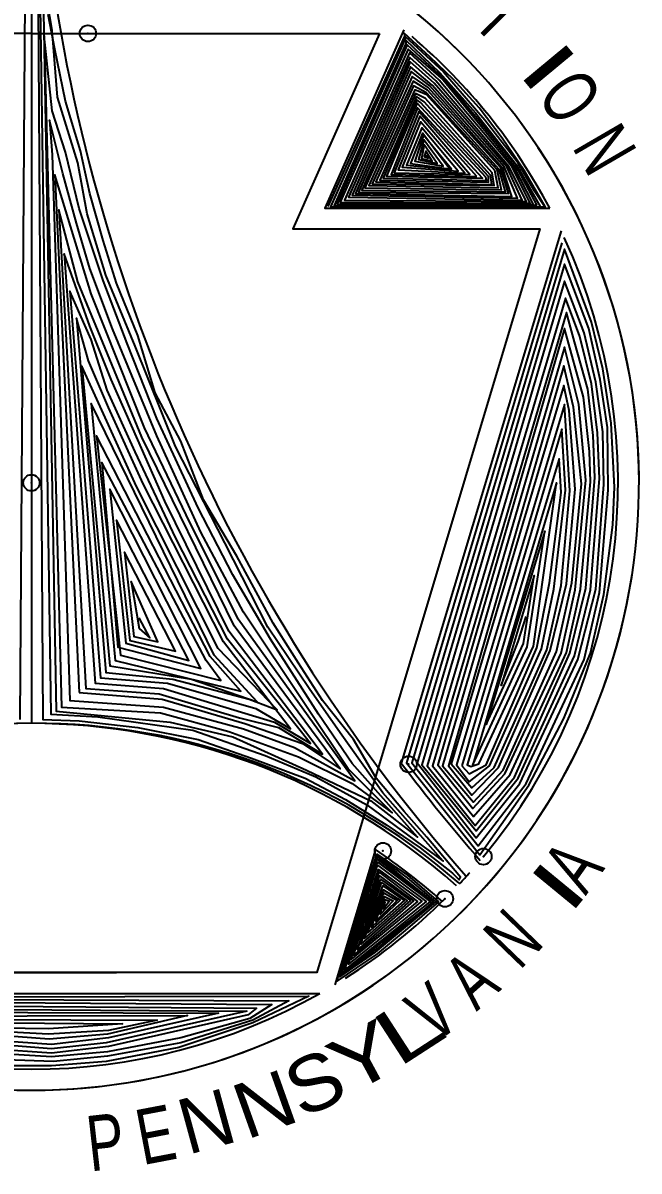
# Model space of a CAD drawing. Extents: x 763.8 to 797.8, y -170.3 to -127.3.
# Drawn here: x 780.741 to 782.194, y -131.5 to -128.791 of the extents above; entities that cross this region are included whole.
import ezdxf
from ezdxf.enums import TextEntityAlignment as Align

# ---------------------------------------------------------------- set-up
doc = ezdxf.new("R2010")
doc.units = 0
doc.header["$LTSCALE"] = 0.077
doc.header["$PDMODE"] = 32
doc.header["$PDSIZE"] = 0.0385
doc.layers.add('1', color=7, linetype='Continuous', lineweight=35)
doc.layers.add('2', color=7, linetype='Continuous')

msp = doc.modelspace()

# ---------------------------------------------------------------- linework, layer by layer
at = {"layer": '1'}
for p, q in [((780.76075, -128.49192), (780.76075, -130.44333)), ((780.75875, -128.81508), (779.93925, -128.81508)), ((780.76275, -128.81508), (781.58217, -128.81508)), ((782.01025, -129.28092), (781.63325, -130.53733)), ((781.57208, -130.74142), (781.47642, -131.06025)), ((780.08033, -131.08092), (781.44117, -131.08092))]:
    msp.add_line(p, q, dxfattribs=at)
for points in [[(780.74633, -128.50825), (780.73367, -130.434)], [(780.77517, -128.50825), (780.78775, -130.434), (780.873, -130.43717), (781.01192, -130.45292), (781.154, -130.48142), (781.28025, -130.52558), (781.40658, -130.57292), (781.50125, -130.62342), (781.59917, -130.68342), (781.67808, -130.73708), (781.75383, -130.79708), (781.76958, -130.81283), (781.77275, -130.80658), (781.69383, -130.71183), (781.64017, -130.65183), (781.57392, -130.57292), (781.52025, -130.48142), (781.44758, -130.38983), (781.39075, -130.30142), (781.33075, -130.20667), (781.24558, -130.04883), (781.16658, -129.91625), (781.11292, -129.77733), (781.053, -129.66367), (781.01192, -129.52792), (780.96142, -129.40483), (780.92983, -129.30383), (780.89825, -129.19333), (780.87617, -129.09225), (780.84142, -128.97542), (780.81617, -128.85233), (780.80042, -128.77025)], [(780.7815, -128.75133), (780.80675, -130.42142), (780.91725, -130.42775), (781.14133, -130.45925), (781.31183, -130.51925), (781.43183, -130.56975), (781.55175, -130.63608), (781.73175, -130.76867), (781.58967, -130.60767), (781.48867, -130.46558), (781.416, -130.36142), (781.31817, -130.21617), (781.21717, -130.01733), (781.10033, -129.79), (781.00558, -129.55317), (780.93617, -129.38592), (780.89192, -129.24067), (780.86983, -129.12067), (780.8225, -128.966), (780.80983, -128.80808), (780.78775, -128.67867), (780.81933, -130.41508), (781.08775, -130.44033), (781.23608, -130.47508), (781.40975, -130.554), (781.56125, -130.62658), (781.67175, -130.71183), (781.51708, -130.53817), (781.43817, -130.42142), (781.3245, -130.24458), (781.23608, -130.09308), (781.154, -129.93517), (781.05617, -129.72367), (780.98667, -129.54692), (780.92983, -129.3985), (780.873, -129.228), (780.84142, -129.09542), (780.80983, -128.99758), (780.79092, -128.82075), (780.832, -130.40558), (781.06558, -130.41825), (781.22658, -130.46242), (781.39075, -130.52242), (781.51708, -130.58558), (781.61175, -130.655), (781.50758, -130.55083), (781.40658, -130.39933), (781.26133, -130.18142), (781.16033, -129.992), (781.05617, -129.76475), (780.95192, -129.51217), (780.89825, -129.37008), (780.86667, -129.26275), (780.83517, -129.14592), (780.80358, -129.01967), (780.80983, -129.10175), (780.85092, -130.38983), (781.07192, -130.40558), (781.26133, -130.45608), (781.38125, -130.50033), (781.52333, -130.57925), (781.24875, -130.19725), (781.12558, -129.951), (781.02775, -129.74575), (780.90142, -129.43008), (780.81617, -129.14908), (780.873, -130.37083)], [(781.63958, -128.80683), (781.45258, -129.22758), (781.98342, -129.22758)], [(779.93925, -128.81508), (780.1445, -129.27675), (779.56125, -129.27675), (780.08775, -131.03175), (780.96133, -131.03175)], [(781.58217, -128.81508), (781.377, -129.27675), (781.96017, -129.27675), (781.43367, -131.03175), (780.56017, -131.03175)], [(781.46058, -129.22358), (781.64142, -128.82158), (781.73275, -128.90617), (781.83008, -129.01917), (781.90675, -129.11742), (781.94508, -129.18325), (781.97258, -129.2255), (781.46742, -129.22458), (781.64242, -128.8295), (781.72392, -128.90808), (781.80842, -129.00242), (781.90475, -129.12533), (781.96075, -129.22358), (781.97258, -129.22458), (781.92342, -129.13908), (781.87133, -129.06242), (781.81725, -128.99067), (781.75633, -128.92383), (781.70033, -128.87075), (781.64042, -128.81475), (781.64433, -128.83933), (781.47525, -129.22158), (781.95292, -129.21967), (781.90375, -129.12725), (781.8055, -129.00733), (781.73175, -128.92092), (781.64733, -128.84225), (781.48217, -129.21767), (781.94508, -129.21867), (781.89883, -129.12825), (781.72783, -128.92092), (781.64925, -128.85208), (781.48908, -129.21375), (781.93725, -129.21575), (781.89392, -129.12925), (781.72292, -128.92583), (781.65225, -128.86092), (781.49892, -129.20883), (781.92833, -129.21175), (781.88708, -129.12925), (781.71508, -128.92675), (781.65317, -128.87175), (781.50875, -129.20192), (781.9185, -129.20883), (781.88217, -129.13025), (781.71117, -128.93267), (781.65417, -128.8825), (781.51758, -129.197), (781.90775, -129.20392), (781.87625, -129.13025), (781.70625, -128.93758), (781.65517, -128.89433), (781.52542, -129.19308), (781.89392, -129.2), (781.87233, -129.13217), (781.70033, -128.93858), (781.65617, -128.90517), (781.53233, -129.19017), (781.88608, -129.19308), (781.86842, -129.13217), (781.69642, -128.9425), (781.65908, -128.91692), (781.54017, -129.18525), (781.87925, -129.18917), (781.8645, -129.13608), (781.69542, -128.94942), (781.66108, -128.92775), (781.54708, -129.17933), (781.86942, -129.18425), (781.85958, -129.13708), (781.6925, -128.95525), (781.66208, -128.93858), (781.55683, -129.17442), (781.8615, -129.17933), (781.85367, -129.13908), (781.6935, -128.96017), (781.665, -128.94842), (781.56475, -129.1705), (781.85267, -129.17442), (781.84775, -129.144), (781.6905, -128.969), (781.66692, -128.95725), (781.57358, -129.16558), (781.84675, -129.1715), (781.84383, -129.14992), (781.68758, -128.97692), (781.66892, -128.96408), (781.58242, -129.16167), (781.83892, -129.16658), (781.83892, -129.15283), (781.67875, -128.97783), (781.66992, -128.972), (781.59025, -129.15675), (781.834, -129.16267), (781.833, -129.15475), (781.67092, -128.97983), (781.59817, -129.15183), (781.82517, -129.15675), (781.67183, -128.99067), (781.609, -129.14792), (781.81142, -129.15283)], [(781.81142, -129.15283), (781.67483, -128.9995), (781.61683, -129.144), (781.79475, -129.14792), (781.67675, -129.01033), (781.62567, -129.13708), (781.78292, -129.14492), (781.67875, -129.02408), (781.6355, -129.13117), (781.76717, -129.14), (781.68175, -129.03783), (781.64533, -129.12625), (781.7475, -129.13517), (781.68367, -129.05058), (781.65517, -129.12233), (781.75142, -129.13517), (781.68567, -129.0555), (781.665, -129.11642), (781.73175, -129.12825), (781.68658, -129.06633), (781.67383, -129.1125), (781.71808, -129.12233), (781.68758, -129.07808), (781.68075, -129.11058), (781.70625, -129.11642), (781.6915, -129.09283), (781.68758, -129.10567), (781.69642, -129.10958), (781.6915, -129.10367)], [(780.873, -130.37083), (781.06875, -130.38667), (781.2645, -130.4435), (781.40025, -130.49083), (781.48867, -130.55083), (781.23925, -130.213), (781.02142, -129.76792), (780.86983, -129.40167), (780.82567, -129.23117), (780.88883, -130.36142), (781.06242, -130.374), (781.25183, -130.43083), (781.34342, -130.45292), (781.44758, -130.51608), (781.22658, -130.22567), (781.07508, -129.91942), (781.01192, -129.77417), (780.94875, -129.63217), (780.89825, -129.50583), (780.83825, -129.33533), (780.91092, -130.34875), (781.07192, -130.36142), (781.33392, -130.44033), (781.41917, -130.49083), (781.22342, -130.24458), (781.10033, -130.00467), (781.00558, -129.80258), (780.93933, -129.65742), (780.90142, -129.53742), (780.85092, -129.42375), (780.9235, -130.33617), (781.08142, -130.34875), (781.28975, -130.40875), (781.37183, -130.45608), (781.214, -130.25092), (781.02458, -129.87842), (780.9425, -129.69842), (780.89508, -129.58792), (780.86667, -129.48692), (780.93617, -130.3235), (781.094, -130.33933), (781.274, -130.38667), (781.34025, -130.41192), (781.20133, -130.26667), (781.00875, -129.88467), (780.87933, -129.60058), (780.94567, -130.30775), (781.13825, -130.33933), (781.29292, -130.393), (781.19183, -130.2825), (780.90142, -129.68892), (780.95825, -130.29508), (781.255, -130.36775), (781.18242, -130.28567), (780.91408, -129.76475), (780.97092, -130.2825), (781.20767, -130.34242), (781.17292, -130.29508), (780.92667, -129.82783), (780.96458, -130.2635), (781.16033, -130.314), (780.94567, -129.891), (780.9835, -130.25408), (781.13192, -130.29508), (780.96142, -129.96358), (780.993, -130.24775), (781.10033, -130.273), (780.98033, -130.03942), (781.00242, -130.23825), (781.05925, -130.25092), (780.99617, -130.10883), (781.01508, -130.21933), (781.04033, -130.24142), (781.01508, -130.19408)], [(782.01217, -129.3095), (781.64583, -130.537), (781.8185, -130.75383), (781.93425, -130.58958), (782.01642, -130.43167), (782.07958, -130.278), (782.11117, -130.139), (782.13217, -129.97483), (782.13642, -129.88642), (782.128, -129.73483), (782.109, -129.60642), (782.08167, -129.49692), (782.0185, -129.32425), (781.6585, -130.537), (781.81425, -130.73283), (781.92792, -130.58542), (782.06483, -130.29275), (782.10058, -130.13483), (782.12167, -129.89275), (782.11958, -129.74533), (782.10275, -129.63158), (782.07533, -129.51158), (782.0185, -129.36), (781.67108, -130.537), (781.81008, -130.71383), (781.91325, -130.58542), (782.05008, -130.29275), (782.09217, -130.12642), (782.11117, -129.88008), (782.109, -129.75583), (782.09217, -129.63792), (782.06483, -129.52217), (782.0185, -129.4), (781.68167, -130.54117), (781.81008, -130.697), (781.909, -130.57275), (782.04167, -130.28433), (782.07958, -130.1285), (782.10058, -129.86533), (782.09642, -129.75792), (782.08167, -129.64217), (782.05425, -129.53058), (782.02058, -129.44), (781.69425, -130.54333), (781.80792, -130.68442), (781.90058, -130.57067), (782.03117, -130.278), (782.069, -130.12433), (782.09008, -129.86325), (782.08583, -129.76425), (782.07325, -129.65483), (782.04167, -129.54325), (782.02275, -129.47375), (781.70692, -130.54333), (781.80375, -130.66333), (781.89008, -130.56433), (782.02275, -130.27592), (782.05642, -130.12642), (782.07958, -129.87375), (782.07742, -129.80217), (782.06275, -129.67375), (782.0185, -129.51158), (781.7195, -130.54117), (781.80167, -130.64433), (781.87742, -130.56225), (782.01008, -130.278), (782.04375, -130.1285), (782.069, -129.86958), (782.05217, -129.69058), (782.0185, -129.55583), (781.73008, -130.54333), (781.80375, -130.62958), (781.87325, -130.55383), (781.99958, -130.27383), (782.03533, -130.11167), (782.0585, -129.878), (782.03958, -129.69692), (782.01642, -129.60008), (781.74475, -130.54333), (781.7995, -130.61275), (781.86267, -130.5475), (781.98483, -130.27167), (782.02275, -130.11383), (782.04375, -129.89058), (782.029, -129.70533), (782.01642, -129.64633), (781.75108, -130.53908), (781.7995, -130.59592), (781.85217, -130.5475), (781.97633, -130.26958), (782.01008, -130.118), (782.03117, -129.89483), (782.0185, -129.69058), (781.76375, -130.54117), (781.79325, -130.58117), (781.84167, -130.54333), (781.96375, -130.2675), (781.99325, -130.12642), (782.02058, -129.89275), (782.01217, -129.7495), (781.77633, -130.54333)], [(781.77633, -130.54333), (781.79325, -130.56225), (781.83325, -130.54117), (781.95325, -130.26542), (781.98267, -130.11167), (782.01008, -129.899), (782.00583, -129.819), (781.789, -130.54117), (781.79742, -130.54542), (781.81633, -130.53908), (781.94483, -130.26117), (781.99958, -129.87583), (781.80167, -130.54117), (781.93008, -130.26325), (781.97217, -129.98958), (781.83325, -130.44642), (781.92167, -130.25483), (781.94692, -130.09483), (781.869, -130.35383), (781.909, -130.25067), (781.92792, -130.19167)], [(781.57467, -130.7515), (781.64767, -130.802), (781.72133, -130.8645), (781.64275, -130.93267), (781.57608, -130.98742), (781.48125, -131.052), (781.57467, -130.75433), (781.64692, -130.80833), (781.71433, -130.8645), (781.64275, -130.92417), (781.57183, -130.98317), (781.48758, -131.04142), (781.57533, -130.76417), (781.70875, -130.86525), (781.49175, -131.03442), (781.57675, -130.75925), (781.708, -130.8645), (781.58517, -130.96775), (781.4925, -131.03725), (781.57675, -130.77117), (781.70175, -130.86383), (781.50025, -131.02533), (781.57742, -130.77817), (781.69192, -130.86383), (781.50867, -131.01192), (781.57958, -130.788), (781.68208, -130.86308), (781.51425, -131.00075), (781.58092, -130.795), (781.6715, -130.86383), (781.52058, -130.99017), (781.58167, -130.80342), (781.66242, -130.86242), (781.52975, -130.97758), (781.58308, -130.814), (781.5845, -130.81117), (781.65467, -130.86175), (781.53817, -130.96492), (781.58658, -130.81892), (781.64692, -130.86242), (781.54658, -130.95158), (781.58933, -130.82658), (781.63992, -130.86175), (781.55358, -130.9375), (781.5915, -130.83642), (781.63075, -130.861), (781.56275, -130.92417), (781.59217, -130.84342), (781.62375, -130.86175), (781.57325, -130.91017), (781.59358, -130.85192), (781.61392, -130.86242), (781.58375, -130.89467), (781.59425, -130.85892), (781.6055, -130.86308), (781.5915, -130.88133), (781.595, -130.86525), (781.59708, -130.86592)], [(780.11308, -131.08942), (781.41525, -131.08767), (781.28267, -131.1505), (781.10808, -131.20817), (780.937, -131.24133), (780.80783, -131.25175), (780.70308, -131.25175)], [(780.12875, -131.09292), (781.36817, -131.09817), (781.28267, -131.14358), (781.11325, -131.19767), (780.9405, -131.22908), (780.813, -131.24133), (780.69958, -131.23783)], [(780.15142, -131.09817), (781.328, -131.10692), (781.27567, -131.14008), (781.11325, -131.18542), (780.9405, -131.21858), (780.80783, -131.23083), (780.52325, -131.21342)], [(780.18283, -131.10692), (781.29133, -131.11558), (781.27217, -131.13133), (780.94225, -131.20642), (780.80783, -131.22208), (780.5355, -131.20292)], [(780.2335, -131.11558), (781.26867, -131.12258), (780.937, -131.19767), (780.80783, -131.21167), (780.54075, -131.19067)], [(780.30158, -131.12433), (781.20233, -131.12783), (780.94225, -131.18542), (780.80783, -131.20117), (780.5495, -131.18367)], [(780.37142, -131.13483), (781.129, -131.13308), (780.9405, -131.17675), (780.80258, -131.18892), (780.55125, -131.16975)], [(780.44475, -131.14183), (781.05742, -131.14358), (780.94225, -131.168), (780.80083, -131.17675), (780.56517, -131.1645)], [(780.51458, -131.14883), (780.97542, -131.15225), (780.80083, -131.1645), (780.58083, -131.161)]]:
    msp.add_lwpolyline(points, dxfattribs=at)
for centre, radius, start, end in [((780.76073, -129.87583), 1.43338, 0, 351.33483), ((780.76073, -129.87583), 1.43338, 45, 36.33483), ((784.88744, -128.08937), 4.1216, 185.63111, 221.19033), ((780.76073, -129.87583), 1.38388, 27.93098, 49.54566), ((780.76073, -129.87583), 1.38388, 320.40788, 24.731), ((780.75419, -131.9625), 1.51919, 48.36043, 131.28276), ((780.76727, -131.9625), 1.51919, 48.71724, 131.63957), ((784.88744, -128.08937), 4.0721, 216.95274, 221.11343), ((780.75419, -131.9625), 1.46969, 48.36043, 56.18546), ((780.76073, -129.87583), 1.38388, 316.87047, 318.34224), ((780.76073, -129.87583), 1.38388, 302.35636, 314.82306), ((780.76073, -129.87583), 1.38388, 240.55017, 299.44982)]:
    msp.add_arc(centre, radius, start, end, dxfattribs=at)
for p in [(780.89408, -128.81508), (780.76075, -129.87583), (781.6505, -130.54), (781.59, -130.74467), (781.82717, -130.75783), (781.73625, -130.85742)]:
    msp.add_point(p, dxfattribs=at)
at = {"layer": '2'}
msp.add_point((780.76075, -129.87583), dxfattribs=at)

# ---------------------------------------------------------------- texts
at = {"layer": '1'}
for s, rotation, width, p in [('T', 314.64, 0.7, (781.82431, -128.81815)), ('I', 309.693, 1.6, (781.93027, -128.9365)), ('O', 304.951, 0.7, (781.97831, -129.00168)), ('N', 300.196, 0.7, (782.05698, -129.12148)), ('A', 54.831, 0.7, (782.09167, -130.81817)), ('I', 50.549, 1.6, (782.0536, -130.86965)), ('N', 46.035, 0.7, (781.94346, -130.99605)), ('A', 41.728, 0.7, (781.8413, -131.09729)), ('V', 37.196, 0.7, (781.74447, -131.17664)), ('Y', 28.396, 1.3, (781.57492, -131.28717)), ('L', 32.925, 1.5, (781.68668, -131.2187)), ('S', 24.099, 1.1, (781.45561, -131.35071)), ('N', 19.574, 1.1, (781.33273, -131.40358)), ('E', 10.83, 0.75, (781.06593, -131.47817)), ('P', 6.461, 0.75, (780.94281, -131.49632))]:
    msp.add_text(s, height=0.1307, rotation=rotation, dxfattribs=dict(at, width=width)).set_placement(p, align=Align.CENTER)
msp.add_text('N', height=0.1307, rotation=15.28, dxfattribs=at).set_placement((781.19057, -131.44548), align=Align.CENTER)

doc.saveas('drawing.dxf')
